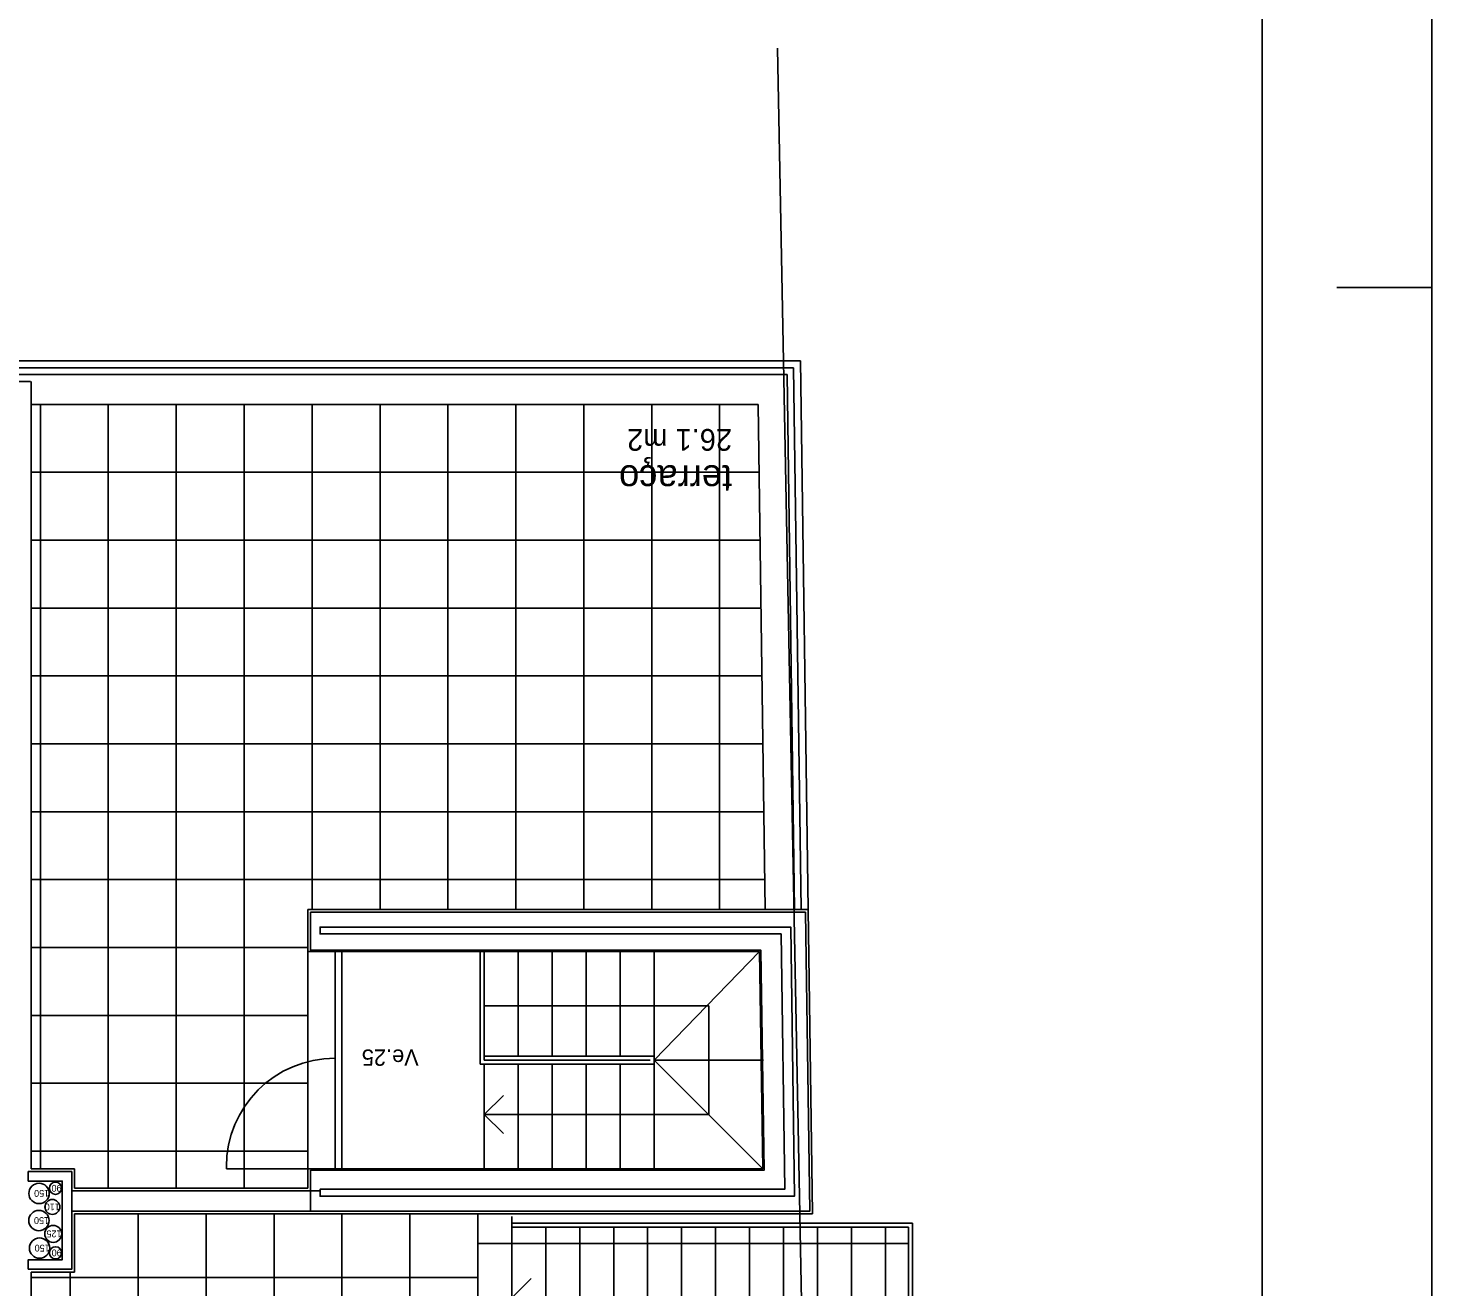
# Model space of a CAD drawing. Extents: x 1278 to 1356, y -253.7 to -224.
# Drawn here: x 1345.63 to 1355.97, y -238.74 to -229.47 of the extents above; entities that cross this region are included whole.
import ezdxf

# ---------------------------------------------------------------- set-up
doc = ezdxf.new("R2010")
doc.units = 0
for name, color, linetype in [('corte', 7, 'Continuous'), ('estereoctomias', 7, 'Continuous'), ('estrutura-eixos', 7, 'Continuous'), ('Level 1', 7, 'Continuous'), ('Level 10', 7, 'Continuous'), ('Level 13', 7, 'Continuous'), ('Level 2', 7, 'Continuous'), ('Level 21', 7, 'Continuous'), ('Level 40', 7, 'Continuous'), ('Level 41', 7, 'Continuous'), ('Level 60', 7, 'Continuous'), ('Level 62', 7, 'Continuous'), ('portas', 7, 'Continuous'), ('revestimentos', 7, 'Continuous')]:
    doc.layers.add(name, color=color, linetype=linetype)

msp = doc.modelspace()

# ---------------------------------------------------------------- linework, layer by layer
at = {"layer": 'corte'}
for p, q in [((1351.354, -235.984), (1351.386, -238.186)), ((1351.246, -236.094), (1351.274, -238.076)), ((1345.634, -237.894), (1345.954, -237.894)), ((1345.954, -237.894), (1345.954, -238.614)), ((1347.712, -237.884), (1351.05, -237.884)), ((1345.634, -237.964), (1345.884, -237.964)), ((1345.884, -237.964), (1345.884, -238.544)), ((1345.954, -238.036), (1347.712, -238.036)), ((1347.782, -238.076), (1351.274, -238.076)), ((1345.954, -238.186), (1351.386, -238.186)), ((1345.884, -238.544), (1345.634, -238.544)), ((1345.954, -238.614), (1345.634, -238.614))]:
    msp.add_line(p, q, dxfattribs=at)
at = {"layer": 'estereoctomias'}
msp.add_line((1348.943, -240.634), (1348.943, -238.206), dxfattribs=at)
for points in [[(1345.954, -238.036), (1347.782, -238.036), (1347.782, -238.076), (1351.274, -238.076), (1351.246, -236.094), (1347.782, -236.094), (1347.782, -236.144), (1351.176, -236.144), (1351.202, -238.024), (1347.782, -238.024), (1347.782, -238.037), (1347.712, -238.035), (1347.712, -237.884), (1351.05, -237.884), (1351.027, -236.264), (1347.712, -236.264), (1347.712, -235.984), (1351.354, -235.984), (1351.386, -238.186), (1345.954, -238.186)], [(1345.634, -238.614), (1345.954, -238.614), (1345.954, -237.894), (1345.634, -237.894), (1345.634, -237.964), (1345.884, -237.964), (1345.884, -238.544), (1345.634, -238.544)]]:
    msp.add_lwpolyline(points, close=True, dxfattribs=at)
at = {"layer": 'estrutura-eixos'}
msp.add_line((1351.148, -229.62), (1351.553, -250.792), dxfattribs=at)
at = {"layer": 'Level 1'}
for p, q in [((1351.354, -235.984), (1347.712, -235.984)), ((1347.712, -236.264), (1347.712, -235.984)), ((1351.246, -236.094), (1347.782, -236.094)), ((1347.782, -236.144), (1347.782, -236.094)), ((1351.176, -236.144), (1347.782, -236.144)), ((1351.176, -236.144), (1351.202, -238.024)), ((1347.712, -236.264), (1351.027, -236.264)), ((1351.027, -236.264), (1351.05, -237.884)), ((1347.712, -237.884), (1347.712, -238.186)), ((1347.782, -238.024), (1351.202, -238.024)), ((1347.782, -238.024), (1347.782, -238.076))]:
    msp.add_line(p, q, dxfattribs=at)
at = {"layer": 'Level 10'}
for p, q in [((1348.943, -240.624), (1348.943, -238.224)), ((1349.193, -239.394), (1349.193, -238.224)), ((1349.443, -239.394), (1349.443, -238.304)), ((1349.693, -239.394), (1349.693, -238.304)), ((1349.943, -239.394), (1349.943, -238.304)), ((1350.193, -239.394), (1350.193, -238.304)), ((1350.443, -239.394), (1350.443, -238.304)), ((1350.693, -239.394), (1350.693, -238.304)), ((1350.943, -239.394), (1350.943, -238.304)), ((1351.193, -240.544), (1351.193, -238.304)), ((1351.443, -240.544), (1351.443, -238.304)), ((1351.693, -240.544), (1351.693, -238.304)), ((1351.943, -240.544), (1351.943, -238.304)), ((1352.113, -238.424), (1348.943, -238.424))]:
    msp.add_line(p, q, dxfattribs=at)
at = {"layer": 'Level 13'}
for p, q in [((1347.892, -237.874), (1347.892, -236.274)), ((1347.942, -237.874), (1347.942, -236.274))]:
    msp.add_line(p, q, dxfattribs=at)
msp.add_arc((1347.892, -237.859), 0.8, 90, 180, dxfattribs=at)
at = {"layer": 'Level 2'}
for p, q in [((1351.318, -231.924), (1345.543, -231.924)), ((1351.268, -231.974), (1345.543, -231.974)), ((1351.268, -231.974), (1351.324, -235.964)), ((1351.318, -231.924), (1351.374, -235.964)), ((1351.219, -232.024), (1345.543, -232.024)), ((1351.219, -232.024), (1351.274, -235.964)), ((1351.007, -232.244), (1345.654, -232.244)), ((1351.007, -232.244), (1351.058, -235.964)), ((1347.692, -236.274), (1347.692, -237.874)), ((1348.96, -237.104), (1348.96, -236.274)), ((1348.99, -237.074), (1348.99, -236.274)), ((1349.24, -237.044), (1349.24, -236.274)), ((1349.49, -237.044), (1349.49, -236.274)), ((1349.74, -237.044), (1349.74, -236.274)), ((1349.99, -237.044), (1349.99, -236.274)), ((1350.24, -237.044), (1350.24, -236.274)), ((1350.24, -237.074), (1351.017, -236.274)), ((1348.99, -236.674), (1350.643, -236.674)), ((1350.643, -237.474), (1350.643, -236.674)), ((1350.24, -237.044), (1348.99, -237.044)), ((1350.24, -237.104), (1350.24, -237.044)), ((1350.24, -237.104), (1348.96, -237.104)), ((1350.211, -237.074), (1348.99, -237.074)), ((1348.99, -237.874), (1348.99, -237.104)), ((1349.24, -237.874), (1349.24, -237.104)), ((1349.49, -237.874), (1349.49, -237.104)), ((1349.74, -237.874), (1349.74, -237.104)), ((1349.99, -237.874), (1349.99, -237.104)), ((1351.047, -237.074), (1350.24, -237.074)), ((1350.24, -237.074), (1351.04, -237.874)), ((1350.24, -237.874), (1350.24, -237.104)), ((1349.131, -237.333), (1348.99, -237.474)), ((1350.643, -237.474), (1348.99, -237.474)), ((1349.131, -237.615), (1348.99, -237.474)), ((1349.193, -238.224), (1349.193, -239.394)), ((1349.193, -238.274), (1352.143, -238.274)), ((1349.193, -238.304), (1352.113, -238.304)), ((1349.443, -238.304), (1349.443, -239.394)), ((1349.693, -238.304), (1349.693, -239.394)), ((1349.943, -238.304), (1349.943, -239.394)), ((1350.193, -238.304), (1350.193, -239.394)), ((1350.443, -238.304), (1350.443, -239.394)), ((1350.693, -238.304), (1350.693, -239.394)), ((1350.943, -238.304), (1350.943, -239.394)), ((1352.113, -238.304), (1352.113, -240.544)), ((1352.143, -238.274), (1352.143, -240.574)), ((1349.335, -238.683), (1349.193, -238.824))]:
    msp.add_line(p, q, dxfattribs=at)
at = {"layer": 'Level 21'}
for p, q in [((1345.723, -237.874), (1345.723, -232.244)), ((1346.223, -238.016), (1346.223, -232.244)), ((1346.723, -238.016), (1346.723, -232.244)), ((1347.223, -238.016), (1347.223, -232.244)), ((1347.723, -235.964), (1347.723, -232.244)), ((1348.223, -235.964), (1348.223, -232.244)), ((1348.723, -235.964), (1348.723, -232.244)), ((1349.223, -235.964), (1349.223, -232.244)), ((1349.723, -235.964), (1349.723, -232.244)), ((1350.223, -235.964), (1350.223, -232.244)), ((1350.723, -235.964), (1350.723, -232.244)), ((1345.654, -232.744), (1351.014, -232.744)), ((1345.654, -233.244), (1351.021, -233.244)), ((1345.654, -233.744), (1351.028, -233.744)), ((1345.654, -234.244), (1351.035, -234.244)), ((1345.654, -234.744), (1351.042, -234.744)), ((1345.654, -235.244), (1351.048, -235.244)), ((1345.654, -235.744), (1351.055, -235.744)), ((1345.654, -236.244), (1347.692, -236.244)), ((1345.654, -236.744), (1347.692, -236.744)), ((1345.654, -237.244), (1347.692, -237.244)), ((1345.654, -237.744), (1347.692, -237.744)), ((1346.443, -238.206), (1346.443, -240.624)), ((1346.943, -238.206), (1346.943, -240.624)), ((1347.443, -238.206), (1347.443, -240.624)), ((1347.943, -238.206), (1347.943, -240.624)), ((1348.443, -238.206), (1348.443, -240.624)), ((1348.943, -238.674), (1345.654, -238.674)), ((1345.943, -238.634), (1345.943, -240.214))]:
    msp.add_line(p, q, dxfattribs=at)
at = {"layer": 'Level 41'}
for centre, radius in [((1345.713, -238.055), 0.075), ((1345.834, -238.017), 0.045), ((1345.811, -238.155), 0.055), ((1345.712, -238.255), 0.075), ((1345.817, -238.353), 0.0625), ((1345.717, -238.458), 0.075), ((1345.835, -238.493), 0.045)]:
    msp.add_circle(centre, radius, dxfattribs=at)
at = {"layer": 'Level 62'}
for p, q in [((1354.716, -253.659), (1354.716, -223.959)), ((1355.966, -231.384), (1355.266, -231.384))]:
    msp.add_line(p, q, dxfattribs=at)
msp.add_lwpolyline([(1355.966, -223.959), (1355.966, -253.659), (1278.016, -253.659), (1278.016, -223.959)], close=True, dxfattribs=at)
at = {"layer": 'portas'}
for p in [(1347.092, -237.859), (1347.892, -237.874)]:
    msp.add_line(p, (1347.093, -237.874), dxfattribs=at)
at = {"layer": 'revestimentos'}
for p, q in [((1345.651, -232.074), (1345.461, -232.074)), ((1345.654, -232.074), (1345.654, -237.874)), ((1347.692, -236.274), (1347.692, -235.964)), ((1351.374, -235.964), (1347.692, -235.964)), ((1351.374, -235.964), (1351.406, -238.206)), ((1347.692, -236.274), (1351.017, -236.274)), ((1351.017, -236.274), (1351.04, -237.874)), ((1345.654, -237.874), (1345.974, -237.874)), ((1345.974, -237.874), (1345.974, -238.016)), ((1347.692, -237.874), (1351.04, -237.874)), ((1347.692, -237.874), (1347.692, -238.016)), ((1345.974, -238.016), (1347.692, -238.016)), ((1345.974, -238.206), (1351.406, -238.206)), ((1345.974, -238.206), (1345.974, -238.634)), ((1345.654, -238.634), (1345.654, -240.214)), ((1345.974, -238.634), (1345.654, -238.634))]:
    msp.add_line(p, q, dxfattribs=at)

# ---------------------------------------------------------------- texts
at = {"layer": 'Level 40'}
msp.add_text('Ve.25', height=0.12, rotation=180, dxfattribs=at).set_placement((1348.508, -236.995))
at = {"layer": 'Level 41'}
for s, p in [('90', (1345.879, -237.992)), ('150', (1345.788, -238.03)), ('110', (1345.866, -238.13)), ('150', (1345.787, -238.23)), ('125', (1345.879, -238.328)), ('150', (1345.792, -238.433)), ('90', (1345.88, -238.468))]:
    msp.add_text(s, height=0.05, rotation=180, dxfattribs=at).set_placement(p)
at = {"layer": 'Level 60'}
for s, height, p in [('26.1 m2', 0.16, (1350.815, -232.425)), ('terraço', 0.2, (1350.815, -232.692))]:
    msp.add_text(s, height=height, rotation=180, dxfattribs=at).set_placement(p)

doc.saveas('drawing.dxf')
